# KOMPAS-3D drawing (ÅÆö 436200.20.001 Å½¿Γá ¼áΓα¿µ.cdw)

Views: Вид 1, Вид 2
Referenced files in C:\Users\ptitsin\Desktop\Базовая грузовые\: ПТФ 436200.20.001 Плита.cdw
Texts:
  Symbol type B
  H14, h14,  IT 14/2.
  Ra 6,3
  Ra 6,3 ( )
  CONTINUOUS_RGB_255_0_0_THICK_0.25
  ACAD_ISO02W100_RGB_0_0_0_SC_0.5_THICK_0.18
  СONTINUOUS_RGB_0_0_0_THICK_0.18
  POLYLINE_STYLE_0.50_RGB_0_0_0
  ACAD_ISO02W100_RGB_0_0_0_SC_1_THICK_0.18
  CONTINUOUS_RGB_0_0_0_THICK_0.18
  CONTINUOUS_RGB_0_0_0_THICK_0.6
  ACAD_ISO10W100_RGB_0_0_0_SC_1_THICK_0.18
  Сталь 45 ГОСТ 1050-88
  ПТФ 436200.20.001
  Плита матриц
  Т. директор
  ООО "ЗАВОД МАРКОН"
  ПТФ 436200.20.001-
Dimensions and other numbers on the sheet: 100; 75; 150; +0,025; 156,5; 370; 460; 78,25; 200; 350; 63; 280; 320; 10; 4 фаски; 40; 46; 4 отв.; 1,5; 15; 18; 84; 8; 260±0,16; 25; 20; 7; 310; 140; 60; +0,032; 1,6; 0,8; 5; 16 отв.; 0,05; 1; 6 отв.; 118; 38; 30; 8х25; 2 отв.; 190; 260; 22; 290; 6; 16х1,5; 4; 1:1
